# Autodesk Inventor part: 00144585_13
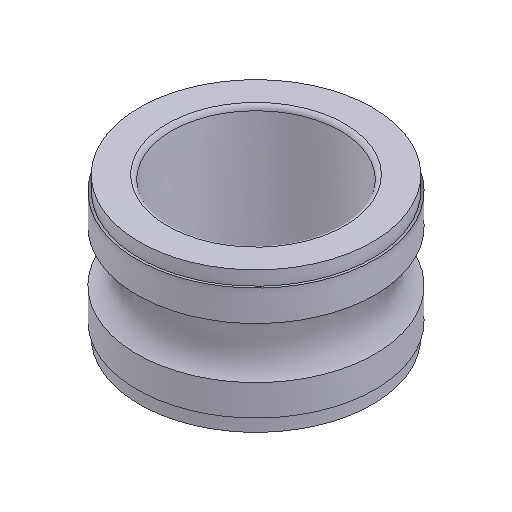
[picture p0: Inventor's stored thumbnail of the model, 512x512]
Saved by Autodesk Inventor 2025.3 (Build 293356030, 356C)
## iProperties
Created: 2021-02
Part Number: 00144585_13
Material: Generico
Document SubType Name: Modeling
Designer: R5800u
Density: 1 g/cm^3
Appearance: Default
Author: TraceParts
Sending System: SolidWorks 2021
Last Author: Albert
Last Saved: 2021-07-28
IsFastener: 1
TYPE: CATASM
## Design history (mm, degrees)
feature "Imported1"
node "Solido1"
